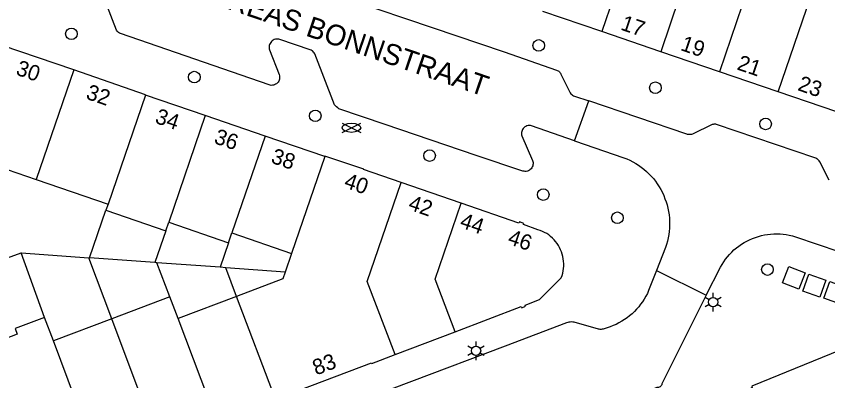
# Model space of a CAD drawing. Extents: x 122462 to 123306, y 485548 to 486417.
# Drawn here: x 122731.7 to 122810, y 485795.5 to 485830.6 of the extents above; entities that cross this region are included whole.
import ezdxf

# ---------------------------------------------------------------- set-up
doc = ezdxf.new("R2010")
doc.units = 0
for name, color, linetype in [('Level 1', 7, 'Continuous'), ('Level 17', 7, 'Continuous'), ('Level 19', 7, 'Continuous'), ('Level 4', 7, 'Continuous'), ('Level 42', 7, 'Continuous'), ('Level 50', 7, 'Continuous'), ('Level 52', 7, 'Continuous'), ('Level 53', 7, 'Continuous'), ('Level 58', 7, 'Continuous'), ('Level 59', 7, 'Continuous')]:
    doc.layers.add(name, color=color, linetype=linetype)

msp = doc.modelspace()

# ---------------------------------------------------------------- linework, layer by layer
at = {"layer": 'Level 1'}
for p, q in [((122788.178, 485829.144), (122782.494, 485831.088)), ((122793.86, 485827.199), (122788.178, 485829.144)), ((122737.224, 485825.433), (122730.311, 485827.81)), ((122799.538, 485825.261), (122793.86, 485827.199)), ((122805.214, 485823.321), (122799.538, 485825.261)), ((122749.906, 485821.036), (122744.138, 485823.015)), ((122810.87, 485821.388), (122805.214, 485823.321)), ((122755.675, 485819.056), (122749.906, 485821.036)), ((122761.443, 485817.077), (122755.675, 485819.056)), ((122726.685, 485817.241), (122733.6, 485814.869)), ((122733.6, 485814.869), (122740.527, 485812.492)), ((122774.61, 485812.59), (122768.82, 485814.579)), ((122740.527, 485812.492), (122740.324, 485811.9)), ((122740.324, 485811.9), (122746.092, 485809.921)), ((122746.092, 485809.921), (122746.377, 485810.751)), ((122746.377, 485810.751), (122752.146, 485808.771)), ((122752.146, 485808.771), (122752.47, 485809.715)), ((122752.47, 485809.715), (122758.238, 485807.735)), ((122758.238, 485807.735), (122757.622, 485805.94)), ((122746.498, 485803.54), (122740.891, 485801.421)), ((122747.285, 485801.459), (122746.498, 485803.54)), ((122752.935, 485803.594), (122747.285, 485801.459)), ((122735.257, 485799.292), (122734.399, 485801.564)), ((122740.891, 485801.421), (122735.257, 485799.292)), ((122768.229, 485797.98), (122774.016, 485800.181))]:
    msp.add_line(p, q, dxfattribs=at)
for points in [[(122744.138, 485823.015), (122744.15, 485823.049), (122737.224, 485825.433)], [(122768.82, 485814.579), (122765.184, 485815.833), (122765.199, 485815.88), (122761.459, 485817.13), (122761.443, 485817.077)], [(122774.016, 485800.181), (122780.405, 485802.611), (122780.448, 485802.499), (122780.829, 485802.645), (122780.786, 485802.757), (122782.179, 485803.289), (122784.261, 485805.391), (122784.339, 485805.609), (122784.402, 485805.832), (122784.45, 485806.058), (122784.483, 485806.287), (122784.502, 485806.518), (122784.504, 485806.749), (122784.492, 485806.98), (122784.464, 485807.21), (122784.421, 485807.438), (122784.364, 485807.662), (122784.291, 485807.881), (122784.204, 485808.096), (122784.104, 485808.304), (122783.99, 485808.506), (122783.862, 485808.699), (122783.722, 485808.883), (122783.571, 485809.058), (122783.408, 485809.223), (122783.235, 485809.376), (122783.051, 485809.518), (122782.859, 485809.647), (122782.659, 485809.763), (122782.452, 485809.866), (122782.238, 485809.954), (122782.019, 485810.029), (122780.618, 485810.515), (122780.656, 485810.627), (122780.221, 485810.777), (122780.183, 485810.666), (122774.61, 485812.59)], [(122757.622, 485805.94), (122757.395, 485805.28), (122752.935, 485803.594)], [(122734.399, 485801.564), (122731.56, 485800.491), (122731.771, 485799.934), (122728.981, 485798.88)], [(122828.305, 485782.943), (122822.924, 485796.069), (122820.089, 485797.088), (122813.635, 485799.409), (122802.643, 485794.923), (122802.691, 485794.803), (122802.566, 485794.755)], [(122756.679, 485793.679), (122765.964, 485797.168), (122765.969, 485797.12), (122768.229, 485797.98)]]:
    msp.add_lwpolyline(points, dxfattribs=at)
at = {"layer": 'Level 17'}
for p, q in [((122785.556, 485818.61), (122786.917, 485822.471)), ((122793.465, 485806.104), (122798.258, 485803.714))]:
    msp.add_line(p, q, dxfattribs=at)
for points in [[(122785.556, 485818.61), (122781.392, 485820.053), (122781.284, 485820.073), (122781.174, 485820.077), (122781.064, 485820.066), (122780.957, 485820.039), (122780.856, 485819.997), (122780.761, 485819.941), (122780.675, 485819.873), (122780.599, 485819.793), (122780.536, 485819.703), (122780.486, 485819.605), (122780.45, 485819.501), (122780.429, 485819.392), (122780.424, 485819.283), (122780.435, 485819.173), (122780.461, 485819.066), (122781.488, 485816.701), (122781.523, 485816.6), (122781.542, 485816.495), (122781.547, 485816.388), (122781.537, 485816.281), (122781.512, 485816.177), (122781.473, 485816.078), (122781.419, 485815.985), (122781.354, 485815.901), (122781.277, 485815.826), (122781.19, 485815.764), (122781.095, 485815.714), (122780.995, 485815.678), (122780.89, 485815.656), (122780.783, 485815.65), (122780.676, 485815.658), (122780.572, 485815.682), (122776.069, 485817.181), (122767.279, 485820.169), (122762.813, 485821.687), (122762.691, 485821.769), (122762.578, 485821.863), (122762.476, 485821.968), (122762.385, 485822.084), (122760.473, 485826.987), (122760.428, 485827.077), (122760.37, 485827.16), (122760.301, 485827.234), (122760.221, 485827.296), (122760.134, 485827.347), (122760.04, 485827.384), (122757.105, 485828.383), (122756.998, 485828.408), (122756.889, 485828.419), (122756.78, 485828.414), (122756.672, 485828.395), (122756.567, 485828.36), (122756.469, 485828.312), (122756.378, 485828.251), (122756.296, 485828.177), (122756.226, 485828.094), (122756.167, 485828.001), (122756.122, 485827.901), (122756.091, 485827.796), (122756.074, 485827.687), (122756.073, 485827.578), (122756.086, 485827.469), (122756.115, 485827.363), (122757.046, 485824.983), (122757.075, 485824.879), (122757.089, 485824.772), (122757.088, 485824.664), (122757.072, 485824.557), (122757.041, 485824.453), (122756.996, 485824.355), (122756.938, 485824.264), (122756.868, 485824.182), (122756.787, 485824.11), (122756.696, 485824.051), (122756.599, 485824.004), (122756.496, 485823.972), (122756.389, 485823.955), (122756.281, 485823.952), (122756.174, 485823.965), (122756.069, 485823.992), (122741.715, 485828.943), (122741.623, 485828.986), (122741.539, 485829.043), (122741.464, 485829.112), (122741.401, 485829.191), (122741.35, 485829.279), (122739.467, 485834.113)], [(122763.991, 485832.206), (122771.807, 485829.543), (122778.766, 485827.173), (122783.803, 485825.417), (122783.883, 485825.391), (122783.958, 485825.354), (122784.027, 485825.307), (122784.088, 485825.25), (122784.14, 485825.184), (122784.183, 485825.112), (122784.214, 485825.034), (122785.137, 485823.222), (122785.199, 485823.139), (122785.271, 485823.065), (122785.352, 485823.001), (122785.442, 485822.949), (122785.537, 485822.909), (122786.917, 485822.471)], [(122810.132, 485814.802), (122809.205, 485816.583), (122809.147, 485816.668), (122809.08, 485816.746), (122809.004, 485816.815), (122808.92, 485816.874), (122808.83, 485816.923), (122808.734, 485816.961), (122799.262, 485820.18), (122799.178, 485820.199), (122799.091, 485820.207), (122799.005, 485820.204), (122798.919, 485820.188), (122798.837, 485820.162), (122796.936, 485819.25), (122796.843, 485819.219), (122796.746, 485819.2), (122796.649, 485819.194), (122796.551, 485819.199), (122796.454, 485819.217), (122796.398, 485819.245), (122786.917, 485822.471)], [(122785.556, 485818.61), (122790.31, 485816.973), (122790.607, 485816.853), (122790.899, 485816.719), (122791.184, 485816.572), (122791.461, 485816.412), (122791.731, 485816.238), (122791.992, 485816.052), (122792.244, 485815.854), (122792.487, 485815.644), (122792.719, 485815.423), (122792.941, 485815.192), (122793.152, 485814.95), (122793.35, 485814.698), (122793.537, 485814.437), (122793.711, 485814.168), (122793.873, 485813.891), (122794.021, 485813.607), (122794.156, 485813.316), (122794.276, 485813.019), (122794.383, 485812.716), (122794.475, 485812.409), (122794.553, 485812.098), (122794.616, 485811.783), (122794.664, 485811.466), (122794.697, 485811.147), (122794.714, 485810.827), (122794.717, 485810.507), (122794.705, 485810.186), (122794.677, 485809.867), (122794.635, 485809.549), (122794.577, 485809.233), (122794.505, 485808.921), (122794.418, 485808.612), (122794.317, 485808.308), (122793.465, 485806.104)], [(122798.258, 485803.714), (122799.635, 485806.418), (122799.784, 485806.68), (122799.947, 485806.935), (122800.121, 485807.181), (122800.308, 485807.418), (122800.506, 485807.646), (122800.715, 485807.864), (122800.935, 485808.071), (122801.165, 485808.267), (122801.404, 485808.451), (122801.652, 485808.623), (122801.908, 485808.783), (122802.172, 485808.93), (122802.442, 485809.063), (122802.719, 485809.183), (122803.002, 485809.289), (122803.29, 485809.381), (122803.581, 485809.459), (122803.876, 485809.522), (122804.174, 485809.57), (122804.474, 485809.604), (122804.776, 485809.623), (122805.078, 485809.626), (122805.379, 485809.615), (122805.68, 485809.589), (122805.979, 485809.548), (122806.276, 485809.492), (122806.569, 485809.422), (122806.859, 485809.337), (122813.15, 485807.215)], [(122793.465, 485806.104), (122792.701, 485804.161), (122792.573, 485803.88), (122792.431, 485803.606), (122792.276, 485803.339), (122792.109, 485803.079), (122791.929, 485802.828), (122791.737, 485802.586), (122791.534, 485802.354), (122791.32, 485802.131), (122791.095, 485801.919), (122790.861, 485801.718), (122790.617, 485801.529), (122790.364, 485801.352), (122790.103, 485801.187), (122789.834, 485801.035), (122789.558, 485800.896), (122789.276, 485800.771), (122788.988, 485800.659), (122788.695, 485800.561), (122788.398, 485800.478), (122788.31, 485800.444), (122788.219, 485800.422), (122788.126, 485800.41), (122788.032, 485800.41), (122787.939, 485800.422), (122787.848, 485800.445), (122785.508, 485801.094), (122785.384, 485801.115), (122785.258, 485801.124), (122785.133, 485801.121), (122785.008, 485801.107), (122784.884, 485801.082), (122784.764, 485801.045), (122778.866, 485798.792), (122760.776, 485791.972)], [(122798.258, 485803.714), (122793.982, 485795.152), (122793.957, 485795.072), (122793.918, 485794.999), (122793.866, 485794.934), (122793.802, 485794.88), (122793.73, 485794.839), (122793.651, 485794.812), (122793.568, 485794.8), (122793.485, 485794.804), (122789.721, 485793.264), (122741.957, 485775.215), (122710.091, 485763.174)]]:
    msp.add_lwpolyline(points, dxfattribs=at)
at = {"layer": 'Level 19'}
for p, q in [((122738.751, 485807.318), (122740.324, 485811.9)), ((122746.092, 485809.921), (122745.041, 485806.858)), ((122752.146, 485808.771), (122751.332, 485806.399)), ((122729.811, 485806.956), (122732.143, 485807.8)), ((122732.143, 485807.8), (122738.661, 485807.324)), ((122734.399, 485801.564), (122732.143, 485807.8)), ((122740.891, 485801.421), (122738.661, 485807.324)), ((122738.661, 485807.324), (122738.751, 485807.318)), ((122745.041, 485806.858), (122738.751, 485807.318)), ((122745.249, 485806.843), (122745.041, 485806.858)), ((122751.332, 485806.399), (122745.249, 485806.843)), ((122746.498, 485803.54), (122745.249, 485806.843)), ((122751.891, 485806.358), (122751.332, 485806.399)), ((122752.935, 485803.594), (122751.891, 485806.358)), ((122757.622, 485805.94), (122751.891, 485806.358))]:
    msp.add_line(p, q, dxfattribs=at)
at = {"layer": 'Level 4'}
for p, q in [((122798.077, 485839.535), (122793.86, 485827.199)), ((122805.214, 485823.321), (122809.978, 485837.258)), ((122790.378, 485835.58), (122788.178, 485829.144)), ((122801.738, 485831.696), (122799.538, 485825.261)), ((122737.224, 485825.433), (122733.6, 485814.869)), ((122744.138, 485823.015), (122740.527, 485812.492)), ((122749.906, 485821.036), (122746.377, 485810.751)), ((122755.675, 485819.056), (122752.47, 485809.715)), ((122761.443, 485817.077), (122758.238, 485807.735)), ((122756.679, 485793.679), (122752.935, 485803.594)), ((122745.41, 485789.459), (122740.891, 485801.421)), ((122751.019, 485791.569), (122747.285, 485801.459)), ((122739.779, 485787.319), (122735.257, 485799.292))]:
    msp.add_line(p, q, dxfattribs=at)
for points in [[(122768.229, 485797.98), (122765.543, 485805.044), (122768.82, 485814.579)], [(122774.016, 485800.181), (122772.081, 485805.269), (122774.61, 485812.59)]]:
    msp.add_lwpolyline(points, dxfattribs=at)
at = {"layer": 'Level 42'}
for points in [[(122807.19, 485804.301), (122805.615, 485804.908), (122806.222, 485806.483), (122807.797, 485805.876), (122807.19, 485804.301)], [(122809.228, 485803.519), (122807.583, 485804.093), (122808.157, 485805.738), (122809.802, 485805.164), (122809.228, 485803.519)], [(122811.214, 485802.827), (122809.594, 485803.412), (122810.179, 485805.032), (122811.799, 485804.447), (122811.214, 485802.827)]]:
    msp.add_lwpolyline(points, dxfattribs=at)
at = {"layer": 'Level 50'}
for p, q in [((122798.92, 485803.489), (122798.92, 485803.939)), ((122798.53, 485803.264), (122798.14, 485803.489)), ((122799.699, 485803.489), (122799.309, 485803.264)), ((122798.53, 485802.814), (122798.14, 485802.589)), ((122798.92, 485802.139), (122798.92, 485802.589)), ((122799.699, 485802.589), (122799.309, 485802.814)), ((122776.038, 485798.803), (122776.038, 485799.253)), ((122775.648, 485798.578), (122775.258, 485798.803)), ((122776.817, 485798.803), (122776.427, 485798.578)), ((122775.648, 485798.128), (122775.258, 485797.903)), ((122776.038, 485797.453), (122776.038, 485797.903)), ((122776.817, 485797.903), (122776.427, 485798.128))]:
    msp.add_line(p, q, dxfattribs=at)
for centre in [(122798.92, 485803.039), (122776.038, 485798.353)]:
    msp.add_circle(centre, 0.45, dxfattribs=at)
at = {"layer": 'Level 52'}
for p, q in [((122763.129, 485819.418), (122764.91, 485820.308)), ((122763.129, 485820.308), (122764.91, 485819.418))]:
    msp.add_line(p, q, dxfattribs=at)
msp.add_ellipse((122764.019, 485819.861), major_axis=(0.89, 0), ratio=0.5, dxfattribs=at)
at = {"layer": 'Level 53'}
for centre in [(122736.99, 485828.921), (122782.09, 485827.799), (122748.853, 485824.743), (122793.35, 485823.719), (122760.529, 485821.01), (122803.99, 485820.229), (122771.564, 485817.169), (122782.53, 485813.411), (122789.684, 485811.175), (122804.164, 485806.181)]:
    msp.add_circle(centre, 0.56, dxfattribs=at)

# ---------------------------------------------------------------- texts
at = {"layer": 'Level 58'}
for s, rotation, p in [('17', 341.20341, (122789.912, 485829.343)), ('19', 341.20341, (122795.692, 485827.366)), ('21', 341.20341, (122801.135, 485825.506)), ('30', 341.02201, (122731.542, 485825.009)), ('23', 341.20341, (122807, 485823.501)), ('32', 341.02201, (122738.305, 485822.683)), ('34', 341.02201, (122744.97, 485820.351)), ('36', 341.02201, (122750.667, 485818.396)), ('38', 341.02201, (122756.162, 485816.511)), ('40', 341.02201, (122763.21, 485814.132)), ('42', 341.02201, (122769.411, 485811.999)), ('44', 341.02201, (122774.382, 485810.288)), ('46', 341.02201, (122779.011, 485808.689)), ('83', 20.78776, (122760.606, 485795.953))]:
    msp.add_text(s, height=1.5, rotation=rotation, dxfattribs=at).set_placement(p)
at = {"layer": 'Level 59'}
msp.add_text('ANDREAS BONNSTRAAT', height=2, rotation=341.13203, dxfattribs=at).set_placement((122746.572, 485833.189))

doc.saveas('drawing.dxf')
